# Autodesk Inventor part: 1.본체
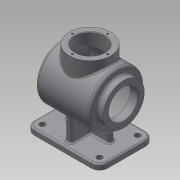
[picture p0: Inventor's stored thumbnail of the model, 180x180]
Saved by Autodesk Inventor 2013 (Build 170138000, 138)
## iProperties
Created: 2016-09
Part Number: 1.본체
Material: 일반
Document SubType Name: Modeling
Designer: default
Density: 1 g/cm^3
Author: default
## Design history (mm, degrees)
sketch "스케치1"
  geometry: L1 (-67.5, -50)-(67.5, -50); L2 (67.5, -50)-(67.5, 50); L3 (67.5, 50)-(-67.5, 50); L4 (-67.5, 50)-(-67.5, -50); L5 (-67.5, -50)-(67.5, 50); L6 (67.5, -50)-(-67.5, 50); 1 further point
  constraints: 12 end point, 2 midpoint, 2 parallel, 1 horizontal, 1 perpendicular
  dimensions: "d0" = 100 distance of L1.end L2.end; "d2" = 135 distance of L2.end L3.end
extrude "돌출1" new body sketch "스케치1" distance "d3" = 10; taper "d4" = 0 deg
sketch "스케치2"
  geometry: L1 (67.5, 0)-(-67.5, 0) reference; L2 (60, 82)-(-62, 82); L3 (48.562, 132)-(-50, 132); L4 (-50, 132)-(-50, 120); L5 (-50, 120)-(-62, 120); L6 (-62, 120)-(-62, 82); A1 r 115 centre (-55, 82) between (60, 82) and (48.562, 132); 1 further point
  constraints: 10 end point, 4 parallel, 2 point on circle, 1 centre point, 1 horizontal alignment, 1 perpendicular
  dimensions: "d5" = 76 diameter of L5 L2; "d8" = 100 diameter of L3 L2; "d9" = 12 distance between parallel lines of L4 L6; "d11" = 82 distance from line of L1 L2.end; "d13" = 50 distance from line of point (0, 0) L4; "d14" = 230 diameter of A1; "d15" = 110 distance from line of L4 L2.start
revolve "회전1" sketch "스케치2" stored, may be unused: angle "d16" = 90 deg
sketch "스케치3"
  geometry: L1 (-62, 44)-(-62, 120) reference; L2 (-62, 82)-(60, 82); L3 (-62, 109)-(-47, 109); L4 (-47, 109)-(-47, 127); L5 (-45, 129)-(46.661, 129); A1 r 115 centre (-55, 82) between (48.562, 32) and (48.562, 132) reference; A2 r 112 centre (-55, 82) between (57, 82) and (46.661, 129); A3 r 2 centre (-45, 127) between (-45, 129) and (-47, 127); 2 further points
  constraints: 8 end point, 5 point on circle, 4 point on line, 2 centre point, 2 parallel, 2 tangent, 1 midpoint, 1 perpendicular
  dimensions: "d17" = 3 radial gap between concentric circles of A1 A2; "d18" = 94 diameter of L5 L2; "d19" = 54 diameter of L3 L2; "d20" = 15 distance between parallel lines of L1 L4; "d38" = 2 radius of A3
revolve "회전2" sketch "스케치3" stored, may be unused: angle "d21" = 90 deg
node "작업 평면1"
sketch "스케치4"
  geometry: L1 (50, 50)-(50, -50) reference; C1 r 38 at (0, 0); 2 further points
  constraints: 1 centre point, 1 horizontal alignment, 1 midpoint
  dimensions: "d23" = 76 diameter of C1; "d24" = 50 distance from line of L1 C1.centre
extrude "돌출2" join sketch "스케치4" stored distance "d25" = 10; taper "d26" = 0 deg
sketch "스케치5"
  geometry: C1 r 38 at (0, 0) reference; C2 r 27 at (0, 0); 1 further point
  constraints: 1 centre point, 1 coincident
  dimensions: "d27" = 54 diameter of C2
extrude "돌출3" cut sketch "스케치5" stored distance "d28" = 10; taper "d29" = 0 deg
sketch "스케치7"
  geometry: C1 r 27 at (0, 0) reference; 2 further points
  constraints: 1 horizontal alignment
  dimensions: "d30" = 32.5 distance of C1.centre point (-32.5, 0)
hole "구멍1" sketch "스케치7" at (-32.5, 0) diameter "d31" = 3.242; stored, may be unused: countersink angle "d35" = 90 deg, drill point angle "d37" = 118 deg; dims "d32" = 8, "d33" = 4, "d34" = 2, "d36" = 10
fillet "모깎기1" dims "d39" = 2
sketch "스케치9"
  geometry: C1 r 27 at (0, 0) reference; 1 further point
  constraints: 1 horizontal alignment
  dimensions: "d43" = 32.5 distance of C1.centre point (-32.5, 0)
hole "구멍2" sketch "스케치9" at (-32.5, 0) diameter "d44" = 3.242; stored, may be unused: countersink angle "d48" = 90 deg, drill point angle "d50" = 118 deg; dims "d45" = 8, "d46" = 4, "d47" = 2, "d49" = 10
chamfer "모따기1" distance "d54" = 1; stored, may be unused: second distance "d55" = 2, angle "d56" = 45 deg
sketch "스케치10"
  geometry: L1 (-50, 10)-(50, 10) reference; L2 (40, 52)-(40, 10); L3 (-40, 10)-(-40, 52); L4 (-40, 10)-(40, 10); A1 r 50 centre (0, 82) between (40, 52) and (-40, 52) reference; 1 further point
  constraints: 6 end point, 2 point on circle, 2 point on line, 1 collinear, 1 parallel, 1 perpendicular
  dimensions: "d57" = 40 distance from line of point (0, 0) L2; "d58" = 40 distance from line of point (0, 0) L3
extrude "돌출4" join sketch "스케치10" stored distance "d59" = 10; taper "d60" = 0 deg
sketch "스케치11"
  geometry: L1 (-50, 32)-(48.562, 32) reference; L2 (67.5, 0)-(-67.5, 0) reference; L3 (-67.5, 0)-(-67.5, 10) reference; L4 (67.5, 10)-(-67.5, 10) reference; L5 (67.5, 0)-(67.5, 10) reference; L6 (67.5, 10)-(-67.5, 10) reference; L7 (-38.075, 32)-(-40, 10); 1 further point
  constraints: 2 end point, 2 point on line
  dimensions: "d61" = 95 deg angle of L4 L7; "d62" = 40 horizontal distance of point (0, 0) L7.end
feature "리브1" sketch "스케치11" dims "d63" = 1, "d64" = 10, "d65" = 0, "d66" = 0, "d67" = 1, "d68" = 1
sketch "스케치12"
  geometry: L1 (-50, 32)-(48.562, 32) reference; L2 (67.5, 10)-(-67.5, 10) reference; L3 (40, 10)-(38.075, 32); 1 further point
  constraints: 2 end point, 2 point on line
  dimensions: "d69" = 95 deg angle of L2 L3; "d70" = 40 horizontal distance of point (0, 0) L3.start
feature "리브2" sketch "스케치12" dims "d71" = 1, "d72" = 10, "d73" = 0, "d74" = 0, "d75" = 1, "d76" = 1
fillet "모깎기2" dims "d77" = 5
fillet "모깎기3" dims "d78" = 15
sketch "스케치14"
  geometry: A1 r 15 centre (52.5, -35) between (52.5, -50) and (67.5, -35) reference; A2 r 15 centre (52.5, 35) between (67.5, 35) and (52.5, 50) reference; A3 r 15 centre (-52.5, 35) between (-52.5, 50) and (-67.5, 35) reference; A4 r 15 centre (-52.5, -35) between (-67.5, -35) and (-52.5, -50) reference; 1 further point
hole "구멍3" sketch "스케치14" at (-52.5, 35), (52.5, 35), (52.5, -35), (-52.5, -35) diameter "d79" = 10; stored, may be unused: countersink angle "d83" = 90 deg, drill point angle "d85" = 0 deg; dims "d80" = 8, "d81" = 4, "d82" = 2, "d84" = 10
fillet "모깎기4" dims "d86" = 3
fillet "모깎기5" dims "d87" = 3
fillet "모깎기6" dims "d88" = 3
node "작업 평면2"
sketch "스케치15"
  geometry: L1 (-40, 51.016)-(-40, 13) reference; L2 (-35, 0)-(35, 0) reference; 2 further points
  constraints: 1 other
  dimensions: "d90" = 82 distance from line of L2 point (0, 82); "d91" = 40 distance from line of L1 point (0, 82)
feature "엠보싱1" sketch "스케치15" dims "d0" = 100, "d2" = 135, "d92" = 0.5, "d93" = 0
node "솔리드1"
pattern_circular "원형 패턴1" dims angle "d41" = 360 deg
pattern_circular "원형 패턴2" dims angle "d52" = 360 deg
node "투영된 루프1"
other parameters: "d22" = 147
